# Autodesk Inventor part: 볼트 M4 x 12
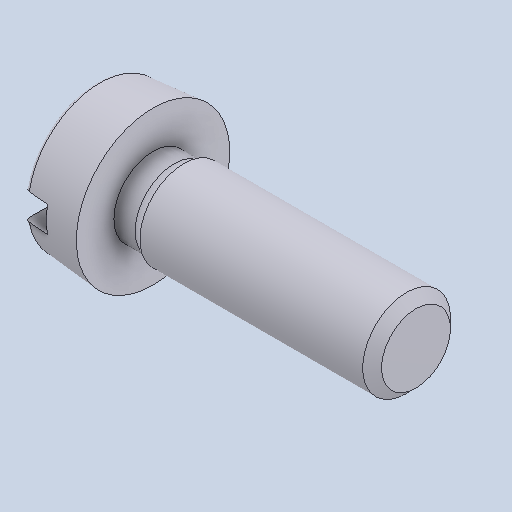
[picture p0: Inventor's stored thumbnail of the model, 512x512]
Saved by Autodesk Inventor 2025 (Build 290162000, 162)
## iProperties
Created: 2025-08
Part Number: 볼트 M4 x 12
Material: 강철, 연강
Description: 6각머리 태핑 나사
Document SubType Name: Modeling
Designer: infra02
Density: 7.85 g/cm^3
Appearance: 기본값
Author: jhkim
Sending System: Autodesk Inventor 2026
Preprocessor: ST-DEVELOPER v20.1
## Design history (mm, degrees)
feature "Solid1"
node "솔리드1"
